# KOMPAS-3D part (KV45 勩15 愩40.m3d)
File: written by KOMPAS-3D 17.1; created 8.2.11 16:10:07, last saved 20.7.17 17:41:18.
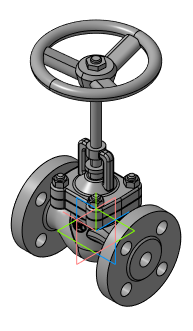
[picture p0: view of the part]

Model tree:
1. Ось X
2. Ось Y
3. Ось Z
4. Операция без истории:2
